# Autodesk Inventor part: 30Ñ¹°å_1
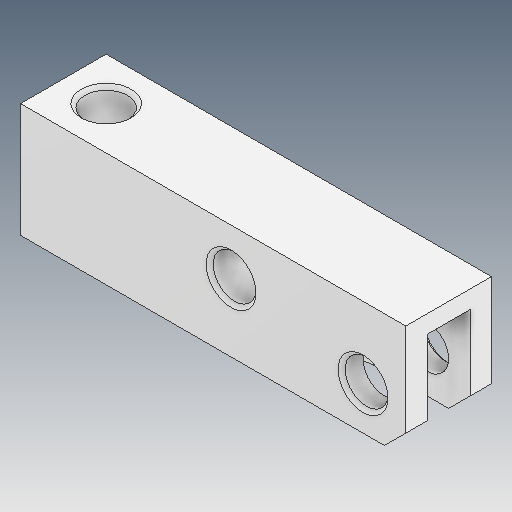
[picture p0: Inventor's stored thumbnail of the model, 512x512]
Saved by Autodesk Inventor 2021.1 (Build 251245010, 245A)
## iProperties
Created: 2021-05
Part Number: 30Ñ¹°å_1
Material: Ogólny
Document SubType Name: Modeling
Designer: user
Density: 1 g/cm^3
Appearance: Domyślna
Author: user
Revision Number: ÈÎºÎ
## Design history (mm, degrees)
feature "ÊäÈë1"
node "Bryła1"
